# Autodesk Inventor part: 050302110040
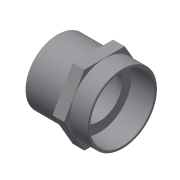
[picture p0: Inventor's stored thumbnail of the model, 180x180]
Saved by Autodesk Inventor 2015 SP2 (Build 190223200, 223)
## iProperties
Created: 2017-10
Part Number: 050302110040
Material: Generic
Description: PLASSON ADAPTOR SOCKET M.F.110-4" CEM-THR
Document SubType Name: Modeling
Designer: KIM
Density: 1 g/cm^3
Appearance: Default
Author: KIM
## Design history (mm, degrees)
derived "050302.ipt"
feature "Solid1::050302.ipt"
tag "TaggingFeature1"
body "Solid1"
other parameters: "d0" = 112, "d3" = 110.072, "d4" = 77, "d8" = 118.8, "d13" = 0, "d14" = 1.1, "d17" = 61, "d18" = 48, "d20" = 88, "G_" = 110.072, "L_" = 61, "H_" = 112
